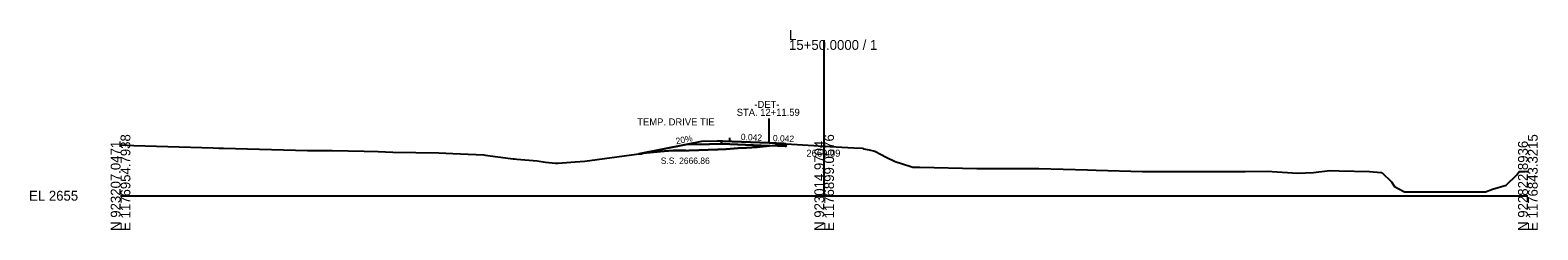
# Model space of a CAD drawing. Extents: x -26 to 1403, y -10 to 9563.
# Drawn here: x -25.7 to 402.8, y 5490.3 to 5547 of the extents above; entities that cross this region are included whole.
import ezdxf

# ---------------------------------------------------------------- set-up
doc = ezdxf.new("R2010")
doc.units = 0
for name, color, linetype in [('Exist Cross Section Cell', 7, 'Continuous'), ('Exist XS Center Line Elevation Label', 7, 'Continuous'), ('Exist XS Ground Line', 7, 'Continuous'), ('Prop XS Ditch Slope Text', 7, 'Continuous'), ('Prop XS Dump Level', 7, 'Continuous'), ('Prop XS Earthwork Shape', 7, 'Continuous'), ('Prop XS EOT Tick Mark', 7, 'Continuous'), ('Prop XS Finish Grade', 7, 'Continuous'), ('Prop XS Finish Grade Earthwork', 7, 'Continuous'), ('Prop XS Finish Grade Pavement', 7, 'Continuous'), ('Prop XS Pvmt Edge Slope', 7, 'Continuous'), ('Prop XS SE Text', 7, 'Continuous'), ('Prop XS Shoulder Borrow Shape', 7, 'Continuous'), ('Prop XS SS Elevation Text', 7, 'Continuous'), ('Prop XS Subgrade Earthwork', 7, 'Continuous'), ('Prop XS Vertical Lines', 7, 'Continuous')]:
    doc.layers.add(name, color=color, linetype=linetype)

msp = doc.modelspace()

# ---------------------------------------------------------------- linework, layer by layer
at = {"layer": 'Exist Cross Section Cell'}
for p, q in [((200, 5500), (200, 5544.25)), ((0, 5500), (200, 5500)), ((200, 5500), (400, 5500))]:
    msp.add_line(p, q, dxfattribs=at)
at = {"layer": 'Exist XS Ground Line'}
for p, q in [((0, 5514.44), (3.8, 5514.3)), ((3.8, 5514.3), (26.3, 5513.58)), ((26.3, 5513.58), (27.93, 5513.53)), ((27.93, 5513.53), (29.29, 5513.49)), ((29.29, 5513.49), (53.13, 5512.85)), ((53.13, 5512.85), (60.13, 5512.9)), ((60.13, 5512.9), (69.24, 5512.68)), ((69.24, 5512.68), (73.2, 5512.54)), ((73.2, 5512.54), (77.41, 5512.4)), ((77.41, 5512.4), (90.42, 5512.19)), ((90.42, 5512.19), (94.46, 5511.99)), ((94.46, 5511.99), (96.63, 5511.9)), ((96.63, 5511.9), (103.3, 5511.59)), ((103.3, 5511.59), (103.63, 5511.55)), ((103.63, 5511.55), (110.82, 5510.58)), ((131.97, 5509.84), (146.67, 5511.79)), ((146.67, 5511.79), (148.06, 5511.94)), ((148.06, 5511.94), (148.53, 5512.05)), ((148.06, 5511.94), (148.53, 5512.05)), ((148.53, 5512.05), (154.56, 5512.65)), ((154.56, 5512.65), (157.11, 5512.87)), ((157.11, 5512.87), (160.64, 5512.87)), ((160.64, 5512.87), (161.58, 5512.9)), ((160.64, 5512.87), (161.58, 5512.9)), ((161.58, 5512.9), (169.77, 5513.12)), ((169.77, 5513.12), (172.12, 5513.26)), ((172.12, 5513.26), (175.5, 5513.5)), ((175.5, 5513.5), (177.95, 5513.64)), ((177.95, 5513.64), (180.92, 5513.79)), ((180.92, 5513.79), (184.44, 5514.21)), ((184.44, 5514.21), (187.09, 5514.5)), ((187.09, 5514.5), (188.36, 5514.57)), ((188.36, 5514.57), (189.06, 5514.75)), ((189.06, 5514.75), (197.06, 5514.28)), ((197.06, 5514.28), (199.53, 5514.12)), ((199.53, 5514.12), (200, 5514.09)), ((200, 5514.09), (208.43, 5513.64)), ((208.43, 5513.64), (210.87, 5513.51)), ((210.87, 5513.51), (211.18, 5513.37)), ((211.18, 5513.37), (212.8, 5513.01)), ((212.8, 5513.01), (214.42, 5512.67)), ((214.42, 5512.67), (217.6, 5510.96)), ((217.6, 5510.96), (220.13, 5509.72)), ((110.82, 5510.58), (111.62, 5510.47)), ((111.62, 5510.47), (111.98, 5510.44)), ((111.98, 5510.44), (112.62, 5510.38)), ((112.62, 5510.38), (118.39, 5509.88)), ((118.39, 5509.88), (120.8, 5509.52)), ((120.8, 5509.52), (123.58, 5509.21)), ((123.58, 5509.21), (124.27, 5509.26)), ((124.27, 5509.26), (129.22, 5509.61)), ((129.22, 5509.61), (131.97, 5509.84)), ((220.13, 5509.72), (224.66, 5508.31)), ((224.66, 5508.31), (225.23, 5508.14)), ((225.23, 5508.14), (227.21, 5508.1)), ((227.21, 5508.1), (243.42, 5507.75)), ((243.42, 5507.75), (250.11, 5507.74)), ((250.11, 5507.74), (261.01, 5507.71)), ((261.01, 5507.71), (274.86, 5507.32)), ((274.86, 5507.32), (277.32, 5507.24)), ((277.32, 5507.24), (290.51, 5506.9)), ((290.51, 5506.9), (291, 5506.9)), ((291, 5506.9), (308.91, 5506.91)), ((308.91, 5506.91), (319.68, 5506.92)), ((319.68, 5506.92), (325.93, 5506.95)), ((325.93, 5506.95), (334.51, 5506.43)), ((339.1, 5506.63), (343.72, 5507.18)), ((343.72, 5507.18), (346.39, 5507.11)), ((346.39, 5507.11), (354.96, 5506.86)), ((354.96, 5506.86), (358.17, 5506.58)), ((396.82, 5505.95), (397.53, 5506.87)), ((397.53, 5506.87), (399.22, 5506.93)), ((399.22, 5506.93), (400, 5506.97)), ((334.51, 5506.43), (339.1, 5506.63)), ((358.17, 5506.58), (358.51, 5506.59)), ((358.51, 5506.59), (361.22, 5503.96)), ((361.22, 5503.96), (362.11, 5502.66)), ((362.11, 5502.66), (363.15, 5502.05)), ((389.96, 5501.87), (393.81, 5503)), ((393.81, 5503), (396.82, 5505.95)), ((363.15, 5502.05), (364.95, 5501.14)), ((364.95, 5501.14), (369.66, 5501.14)), ((369.66, 5501.14), (372.77, 5501.14)), ((372.77, 5501.14), (377.56, 5501.14)), ((377.56, 5501.14), (387.95, 5501.13)), ((387.95, 5501.13), (389.96, 5501.87))]:
    msp.add_line(p, q, dxfattribs=at)
at = {"layer": 'Prop XS Dump Level'}
for p, q in [((184.33, 5514.99), (171.21, 5515.54)), ((184.33, 5514.99), (173.21, 5515.45)), ((188.55, 5514.81), (184.33, 5514.99)), ((189.06, 5514.79), (184.33, 5514.99))]:
    msp.add_line(p, q, dxfattribs=at)
at = {"layer": 'Prop XS Earthwork Shape'}
for p, q in [((147.3, 5511.86), (160.8, 5514.56)), ((148.53, 5512.05), (147.3, 5511.86)), ((154.56, 5512.65), (148.53, 5512.05)), ((157.11, 5512.87), (154.56, 5512.65)), ((160.64, 5512.87), (157.11, 5512.87)), ((160.8, 5514.56), (167.4, 5514.68)), ((169.77, 5513.12), (161.58, 5512.9)), ((167.4, 5514.68), (170.4, 5514.73)), ((172.12, 5513.26), (169.77, 5513.12)), ((170.4, 5514.73), (173.21, 5514.62)), ((175.5, 5513.5), (172.12, 5513.26)), ((173.21, 5514.62), (184.07, 5514.17)), ((177.95, 5513.64), (175.5, 5513.5)), ((180.92, 5513.79), (177.95, 5513.64)), ((184.07, 5514.17), (180.92, 5513.79))]:
    msp.add_line(p, q, dxfattribs=at)
msp.add_lwpolyline([(184.07, 5514.17), (184.37, 5514.2), (187.04, 5514.49), (188.33, 5514.56), (189.03, 5514.75), (189.06, 5514.79), (189.06, 5513.96), (188.88, 5513.97), (184.66, 5514.14)], close=True, dxfattribs=at)
at = {"layer": 'Prop XS EOT Tick Mark'}
msp.add_line((173.21, 5515.45), (173.21, 5516.45), dxfattribs=at)
at = {"layer": 'Prop XS Finish Grade'}
msp.add_line((171.21, 5515.54), (169.62, 5515.51), dxfattribs=at)
at = {"layer": 'Prop XS Finish Grade Earthwork'}
for p, q in [((165.12, 5515.42), (160.8, 5514.56)), ((169.62, 5515.51), (165.12, 5515.42)), ((160.8, 5514.56), (147.3, 5511.86))]:
    msp.add_line(p, q, dxfattribs=at)
at = {"layer": 'Prop XS Finish Grade Pavement'}
for p, q in [((171.21, 5515.54), (184.33, 5514.99)), ((184.33, 5514.99), (189.06, 5514.79))]:
    msp.add_line(p, q, dxfattribs=at)
at = {"layer": 'Prop XS Pvmt Edge Slope'}
msp.add_line((171.21, 5515.54), (170.4, 5514.73), dxfattribs=at)
at = {"layer": 'Prop XS Shoulder Borrow Shape'}
for p, q in [((165.12, 5515.42), (160.8, 5514.56)), ((169.62, 5515.51), (165.12, 5515.42)), ((171.21, 5515.54), (169.62, 5515.51)), ((170.4, 5514.73), (171.21, 5515.54)), ((160.8, 5514.56), (167.4, 5514.68)), ((167.4, 5514.68), (170.4, 5514.73))]:
    msp.add_line(p, q, dxfattribs=at)
at = {"layer": 'Prop XS Subgrade Earthwork'}
for p, q in [((167.4, 5514.68), (160.8, 5514.56)), ((170.4, 5514.73), (167.4, 5514.68)), ((173.21, 5514.62), (170.4, 5514.73)), ((184.33, 5514.16), (173.21, 5514.62)), ((189.06, 5513.96), (184.33, 5514.16)), ((189.06, 5513.96), (189.06, 5514.75))]:
    msp.add_line(p, q, dxfattribs=at)
at = {"layer": 'Prop XS Vertical Lines'}
msp.add_line((184.33, 5514.99), (184.33, 5521.99), dxfattribs=at)

# ---------------------------------------------------------------- texts
at = {"layer": 'Exist Cross Section Cell'}
for s, p in [('L', (190, 5544.25)), ('15+50.0000 / 1', (190, 5541.45)), ('EL 2655', (-26, 5498.6))]:
    msp.add_text(s, height=2.8, dxfattribs=at).set_placement(p)
for s, p in [('N 923207.0471', (0, 5490)), ('E 1176954.7938', (2.8, 5490)), ('N 923014.9704', (200, 5490)), ('E 1176899.0576', (202.8, 5490)), ('N 922822.8936', (400, 5490)), ('E 1176843.3215', (402.8, 5490))]:
    msp.add_text(s, height=2.8, rotation=90, dxfattribs=at).set_placement(p)
at = {"layer": 'Exist XS Center Line Elevation Label'}
msp.add_text('2669.09', height=2, dxfattribs=at).set_placement((194.94, 5511.09))
at = {"layer": 'Prop XS Ditch Slope Text'}
msp.add_text('20%', height=1.8, rotation=10.9329, dxfattribs=at).set_placement((157.99, 5514.6))
at = {"layer": 'Prop XS Dump Level'}
for s, height, p in [('Case1', 0.04, (165.12, 5515.26)), ('Eop', 0.3, (189.16, 5514.3))]:
    msp.add_text(s, height=height, dxfattribs=at).set_placement(p)
at = {"layer": 'Prop XS SE Text'}
for p in [(176.28, 5515.83), (185.39, 5515.51)]:
    msp.add_text('0.042', height=1.8, rotation=357.6196, dxfattribs=at).set_placement(p)
at = {"layer": 'Prop XS SS Elevation Text'}
msp.add_text('S.S. 2666.86', height=1.8, dxfattribs=at).set_placement((153.55, 5509.05))
at = {"layer": 'Prop XS Vertical Lines'}
for s, p in [('STA. 12+11.59', (175.13, 5522.7)), ('-DET-', (180.16, 5524.95)), ('TEMP. DRIVE TIE', (146.87, 5519.98))]:
    msp.add_text(s, height=2, dxfattribs=at).set_placement(p)

doc.saveas('drawing.dxf')
